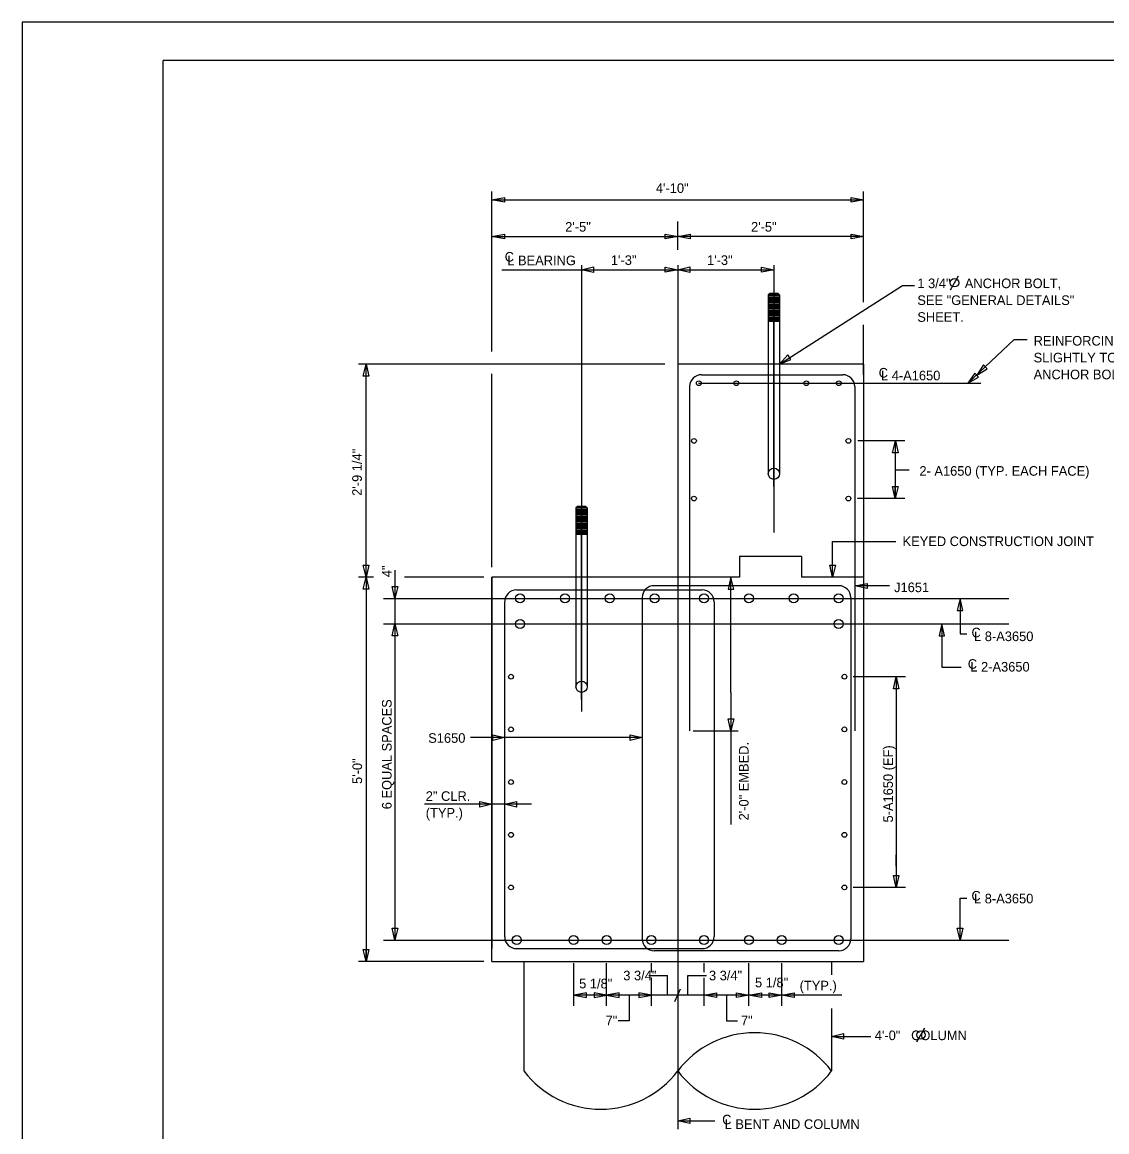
# Model space of a CAD drawing. Extents: x 1970675.2 to 1970711.3, y 796145.2 to 796167.2.
# Drawn here: x 1970675.24 to 1970689.34, y 796152.81 to 796167.25 of the extents above; entities that cross this region are included whole.
import ezdxf

# ---------------------------------------------------------------- set-up
doc = ezdxf.new("R2010")
doc.units = 0
for name, color, linetype in [('BR_AUTO DIMENSION', 7, 'Continuous'), ('BR_BORDER LINES', 7, 'Continuous'), ('BR_CENTER LINES', 7, 'Continuous'), ('BR_CONCRETE', 7, 'Continuous'), ('BR_REBAR', 7, 'Continuous'), ('BR_STRUCTURAL STEEL', 7, 'Continuous'), ('BR_TEXT', 7, 'Continuous'), ('Level 31', 7, 'Continuous')]:
    doc.layers.add(name, color=color, linetype=linetype)

msp = doc.modelspace()

# ---------------------------------------------------------------- linework, layer by layer
at = {"layer": 'BR_AUTO DIMENSION'}
for p, q in [((1970681.342, 796162.965), (1970681.342, 796165.043)), ((1970686.176, 796163.606), (1970686.176, 796165.043)), ((1970681.342, 796164.935), (1970686.176, 796164.935)), ((1970683.759, 796164.287), (1970683.759, 796164.655)), ((1970681.342, 796164.46), (1970683.759, 796164.46)), ((1970686.176, 796164.46), (1970683.759, 796164.46)), ((1970681.473, 796164.027), (1970682.509, 796164.027)), ((1970682.509, 796164.027), (1970683.759, 796164.027)), ((1970683.759, 796164.027), (1970685.009, 796164.027)), ((1970685.082, 796162.8), (1970686.682, 796163.82)), ((1970686.682, 796163.82), (1970686.836, 796163.82)), ((1970686.176, 796162.658), (1970686.176, 796163.31)), ((1970683.592, 796162.8), (1970679.609, 796162.8)), ((1970679.707, 796160.029), (1970679.707, 796162.8)), ((1970681.342, 796160.158), (1970681.342, 796162.671)), ((1970686.712, 796161.8), (1970686.1, 796161.8)), ((1970686.588, 796161.8), (1970686.588, 796161.05)), ((1970686.588, 796161.423), (1970686.766, 796161.423)), ((1970686.712, 796161.05), (1970686.097, 796161.05)), ((1970680.082, 796160.119), (1970680.082, 796155.307)), ((1970679.802, 796160.029), (1970679.609, 796160.029)), ((1970679.707, 796160.029), (1970679.707, 796155.029)), ((1970681.238, 796160.029), (1970680.205, 796160.029)), ((1970684.451, 796158.529), (1970684.451, 796160.029)), ((1970686.513, 796159.913), (1970686.06, 796159.913)), ((1970687.192, 796159.419), (1970687.192, 796158.857)), ((1970687.192, 796158.857), (1970687.443, 796158.857)), ((1970686.722, 796158.733), (1970686.04, 796158.733)), ((1970686.599, 796158.733), (1970686.599, 796155.992)), ((1970684.451, 796158.529), (1970684.451, 796156.811)), ((1970683.961, 796158.029), (1970684.543, 796158.029)), ((1970683.296, 796157.941), (1970681.063, 796157.941)), ((1970681.86, 796157.074), (1970680.468, 796157.074)), ((1970686.722, 796155.992), (1970686.04, 796155.992)), ((1970681.238, 796155.029), (1970679.609, 796155.029)), ((1970682.407, 796154.454), (1970682.407, 796155.006)), ((1970682.834, 796154.454), (1970682.834, 796155.006)), ((1970683.417, 796154.891), (1970683.417, 796155.006)), ((1970684.101, 796154.891), (1970684.101, 796155.006)), ((1970684.684, 796154.454), (1970684.684, 796155.006)), ((1970685.111, 796154.454), (1970685.111, 796155.006)), ((1970683.384, 796154.846), (1970683.627, 796154.846)), ((1970683.417, 796154.454), (1970683.417, 796154.815)), ((1970683.627, 796154.592), (1970683.627, 796154.846)), ((1970683.891, 796154.846), (1970684.134, 796154.846)), ((1970683.891, 796154.592), (1970683.891, 796154.846)), ((1970684.101, 796154.454), (1970684.101, 796154.815)), ((1970683.722, 796154.509), (1970683.796, 796154.674)), ((1970685.894, 796154.592), (1970682.407, 796154.592)), ((1970683.127, 796154.592), (1970683.127, 796154.259)), ((1970684.393, 796154.592), (1970684.393, 796154.259)), ((1970683.127, 796154.259), (1970682.983, 796154.259)), ((1970684.393, 796154.259), (1970684.537, 796154.259)), ((1970685.759, 796154.055), (1970686.271, 796154.055)), ((1970683.759, 796152.956), (1970684.242, 796152.956))]:
    msp.add_line(p, q, dxfattribs=at)
for points in [[(1970681.505, 796164.904), (1970681.342, 796164.935), (1970681.505, 796164.967)], [(1970686.013, 796164.967), (1970686.176, 796164.935), (1970686.013, 796164.904)], [(1970681.505, 796164.429), (1970681.342, 796164.46), (1970681.505, 796164.491)], [(1970683.596, 796164.491), (1970683.759, 796164.46), (1970683.596, 796164.429)], [(1970683.921, 796164.429), (1970683.759, 796164.46), (1970683.921, 796164.491)], [(1970686.013, 796164.491), (1970686.176, 796164.46), (1970686.013, 796164.429)], [(1970682.665, 796163.991), (1970682.509, 796164.027), (1970682.665, 796164.063)], [(1970683.596, 796164.058), (1970683.759, 796164.027), (1970683.596, 796163.996)], [(1970683.915, 796163.991), (1970683.759, 796164.027), (1970683.915, 796164.063)], [(1970684.846, 796164.058), (1970685.009, 796164.027), (1970684.846, 796163.996)], [(1970685.189, 796162.919), (1970685.082, 796162.8), (1970685.23, 796162.86)], [(1970679.671, 796162.644), (1970679.707, 796162.8), (1970679.743, 796162.644)], [(1970687.735, 796162.79), (1970687.646, 796162.657), (1970687.784, 796162.738)], [(1970687.621, 796162.683), (1970687.532, 796162.55), (1970687.67, 796162.631)], [(1970686.553, 796161.644), (1970686.589, 796161.8), (1970686.625, 796161.644)], [(1970686.624, 796161.206), (1970686.588, 796161.05), (1970686.552, 796161.206)], [(1970679.743, 796160.185), (1970679.707, 796160.029), (1970679.671, 796160.185)], [(1970685.809, 796160.185), (1970685.773, 796160.029), (1970685.737, 796160.185)], [(1970679.671, 796159.873), (1970679.707, 796160.029), (1970679.743, 796159.873)], [(1970684.487, 796159.873), (1970684.451, 796160.029), (1970684.415, 796159.873)], [(1970680.118, 796159.908), (1970680.082, 796159.752), (1970680.046, 796159.908)], [(1970686.222, 796159.882), (1970686.06, 796159.913), (1970686.222, 796159.944)], [(1970687.465, 796159.596), (1970687.429, 796159.752), (1970687.393, 796159.596)], [(1970680.046, 796159.263), (1970680.082, 796159.419), (1970680.118, 796159.263)], [(1970687.228, 796159.263), (1970687.192, 796159.419), (1970687.156, 796159.263)], [(1970686.563, 796158.577), (1970686.599, 796158.733), (1970686.635, 796158.577)], [(1970684.487, 796158.185), (1970684.451, 796158.029), (1970684.415, 796158.185)], [(1970681.353, 796157.977), (1970681.509, 796157.941), (1970681.353, 796157.905)], [(1970683.14, 796157.977), (1970683.296, 796157.941), (1970683.14, 796157.905)], [(1970681.186, 796157.11), (1970681.342, 796157.074), (1970681.186, 796157.038)], [(1970681.665, 796157.038), (1970681.509, 796157.074), (1970681.665, 796157.11)], [(1970686.635, 796156.148), (1970686.599, 796155.992), (1970686.563, 796156.148)], [(1970680.118, 796155.463), (1970680.082, 796155.307), (1970680.046, 796155.463)], [(1970687.465, 796155.463), (1970687.429, 796155.307), (1970687.393, 796155.463)], [(1970679.743, 796155.185), (1970679.707, 796155.029), (1970679.671, 796155.185)], [(1970682.575, 796154.623), (1970682.413, 796154.592), (1970682.575, 796154.56)], [(1970682.671, 796154.56), (1970682.834, 796154.592), (1970682.671, 796154.623)], [(1970682.996, 796154.623), (1970682.834, 796154.592), (1970682.996, 796154.56)], [(1970683.254, 796154.56), (1970683.417, 796154.592), (1970683.254, 796154.623)], [(1970684.263, 796154.56), (1970684.101, 796154.592), (1970684.263, 796154.623)], [(1970684.522, 796154.623), (1970684.684, 796154.592), (1970684.522, 796154.56)], [(1970684.847, 796154.56), (1970684.684, 796154.592), (1970684.847, 796154.623)], [(1970684.949, 796154.623), (1970685.111, 796154.592), (1970684.949, 796154.56)], [(1970685.274, 796154.56), (1970685.111, 796154.592), (1970685.274, 796154.623)], [(1970685.915, 796154.019), (1970685.759, 796154.055), (1970685.915, 796154.091)], [(1970683.915, 796152.92), (1970683.759, 796152.956), (1970683.915, 796152.992)]]:
    msp.add_lwpolyline(points, close=True, dxfattribs=at)
for points in [[(1970687.532, 796162.55), (1970688.135, 796163.118), (1970688.3, 796163.118)], [(1970685.773, 796160.029), (1970685.773, 796160.492), (1970686.594, 796160.492)], [(1970687.429, 796159.752), (1970687.429, 796159.289), (1970687.517, 796159.289)], [(1970687.429, 796155.307), (1970687.429, 796155.853), (1970687.517, 796155.853)]]:
    msp.add_lwpolyline(points, dxfattribs=at)
at = {"layer": 'BR_BORDER LINES'}
for p in [(1970710.736, 796166.746), (1970677.07, 796145.746)]:
    msp.add_line(p, (1970677.07, 796166.746), dxfattribs=at)
at = {"layer": 'BR_CENTER LINES'}
for p, q in [((1970682.509, 796164.087), (1970682.509, 796158.28)), ((1970683.759, 796164.087), (1970683.759, 796152.849)), ((1970685.009, 796164.087), (1970685.009, 796160.609)), ((1970685.009, 796161.207), (1970685.009, 796163.506)), ((1970684.029, 796162.55), (1970687.699, 796162.55)), ((1970682.509, 796158.436), (1970682.509, 796160.735)), ((1970679.934, 796159.752), (1970688.062, 796159.752)), ((1970679.934, 796159.419), (1970688.062, 796159.419)), ((1970679.934, 796155.307), (1970688.062, 796155.307))]:
    msp.add_line(p, q, dxfattribs=at)
at = {"layer": 'BR_CONCRETE'}
for p, q in [((1970683.759, 796162.8), (1970683.759, 796160.029)), ((1970686.176, 796162.8), (1970683.759, 796162.8)), ((1970686.176, 796162.8), (1970686.176, 796160.029)), ((1970684.564, 796160.298), (1970684.564, 796160.029)), ((1970685.37, 796160.298), (1970684.564, 796160.298)), ((1970685.37, 796160.298), (1970685.37, 796160.029)), ((1970681.342, 796160.029), (1970681.342, 796155.196)), ((1970681.342, 796155.029), (1970681.342, 796160.029)), ((1970683.759, 796160.029), (1970681.342, 796160.029)), ((1970684.564, 796160.029), (1970683.759, 796160.029)), ((1970686.176, 796160.029), (1970685.37, 796160.029)), ((1970686.176, 796160.029), (1970686.176, 796155.029)), ((1970681.342, 796155.029), (1970686.176, 796155.029)), ((1970681.759, 796155.029), (1970681.759, 796153.605)), ((1970685.759, 796155.029), (1970685.759, 796154.856)), ((1970685.759, 796154.418), (1970685.759, 796153.605))]:
    msp.add_line(p, q, dxfattribs=at)
for centre, start, end in [((1970684.759, 796152.851), 37.0023, 142.9977), ((1970682.759, 796154.359), 217.0023, 322.9977), ((1970684.759, 796154.359), 217.0023, 322.9977)]:
    msp.add_arc(centre, 1.252, start, end, dxfattribs=at)
at = {"layer": 'BR_REBAR'}
for p, q in [((1970684.067, 796162.661), (1970685.906, 796162.661)), ((1970683.914, 796162.508), (1970683.914, 796158.029)), ((1970686.06, 796162.508), (1970686.06, 796158.029)), ((1970681.663, 796159.863), (1970684.076, 796159.863)), ((1970685.855, 796159.917), (1970683.452, 796159.917)), ((1970681.509, 796159.709), (1970681.509, 796155.35)), ((1970683.296, 796159.761), (1970683.296, 796155.325)), ((1970684.233, 796159.707), (1970684.233, 796155.352)), ((1970686.009, 796159.764), (1970686.009, 796155.323)), ((1970681.662, 796155.196), (1970684.076, 796155.196)), ((1970685.855, 796155.169), (1970683.452, 796155.169))]:
    msp.add_line(p, q, dxfattribs=at)
for centre, radius in [((1970684.033, 796162.55), 0.0313), ((1970684.521, 796162.55), 0.0313), ((1970685.431, 796162.55), 0.0313), ((1970685.853, 796162.55), 0.0313), ((1970683.97, 796161.8), 0.0313), ((1970685.978, 796161.8), 0.0313), ((1970683.97, 796161.05), 0.0313), ((1970685.978, 796161.05), 0.0313), ((1970681.71, 796159.752), 0.0588), ((1970682.293, 796159.752), 0.0588), ((1970682.876, 796159.752), 0.0588), ((1970683.46, 796159.752), 0.0588), ((1970684.101, 796159.752), 0.0588), ((1970684.684, 796159.752), 0.0588), ((1970685.267, 796159.752), 0.0588), ((1970685.851, 796159.752), 0.0588), ((1970681.71, 796159.419), 0.0588), ((1970685.851, 796159.419), 0.0588), ((1970681.592, 796158.733), 0.0313), ((1970685.926, 796158.733), 0.0313), ((1970681.592, 796158.048), 0.0313), ((1970685.926, 796158.048), 0.0313), ((1970681.592, 796157.363), 0.0313), ((1970685.926, 796157.363), 0.0313), ((1970681.592, 796156.677), 0.0313), ((1970685.926, 796156.677), 0.0313), ((1970681.592, 796155.992), 0.0313), ((1970685.926, 796155.992), 0.0313), ((1970681.667, 796155.307), 0.0588), ((1970682.404, 796155.307), 0.0588), ((1970682.834, 796155.307), 0.0588), ((1970683.417, 796155.307), 0.0588), ((1970684.101, 796155.307), 0.0588), ((1970684.684, 796155.307), 0.0588), ((1970685.112, 796155.307), 0.0588), ((1970685.851, 796155.307), 0.0588)]:
    msp.add_circle(centre, radius, dxfattribs=at)
for centre, start, end in [((1970684.07, 796162.505), 91.025, 178.975), ((1970685.904, 796162.505), 1.025, 88.975), ((1970681.665, 796159.707), 91.025, 178.975), ((1970683.452, 796159.761), 90, 180), ((1970684.076, 796159.707), 0, 90), ((1970685.853, 796159.761), 1.025, 88.975), ((1970681.665, 796155.352), 181.025, 268.975), ((1970683.452, 796155.325), 180, 270), ((1970684.076, 796155.352), 270, 0), ((1970685.853, 796155.325), 271.025, 358.975)]:
    msp.add_arc(centre, 0.156, start, end, dxfattribs=at)
at = {"layer": 'BR_STRUCTURAL STEEL'}
for p, q in [((1970684.954, 796163.717), (1970684.936, 796163.699)), ((1970685.082, 796163.699), (1970684.936, 796163.699)), ((1970684.936, 796163.699), (1970684.936, 796162.8)), ((1970685.082, 796163.681), (1970684.936, 796163.681)), ((1970685.082, 796163.662), (1970684.936, 796163.662)), ((1970685.082, 796163.644), (1970684.936, 796163.644)), ((1970685.082, 796163.626), (1970684.936, 796163.626)), ((1970685.082, 796163.608), (1970684.936, 796163.608)), ((1970685.082, 796163.59), (1970684.936, 796163.59)), ((1970685.064, 796163.717), (1970684.954, 796163.717)), ((1970685.082, 796163.699), (1970685.064, 796163.717)), ((1970685.082, 796163.699), (1970685.082, 796162.8)), ((1970685.082, 796163.571), (1970684.936, 796163.571)), ((1970685.082, 796163.553), (1970684.936, 796163.553)), ((1970685.082, 796163.535), (1970684.936, 796163.535)), ((1970685.082, 796163.517), (1970684.936, 796163.517)), ((1970685.082, 796163.498), (1970684.936, 796163.498)), ((1970685.082, 796163.48), (1970684.936, 796163.48)), ((1970685.082, 796163.462), (1970684.936, 796163.462)), ((1970685.082, 796163.444), (1970684.936, 796163.444)), ((1970685.082, 796163.426), (1970684.936, 796163.426)), ((1970685.082, 796163.407), (1970684.936, 796163.407)), ((1970685.082, 796163.389), (1970684.936, 796163.389)), ((1970685.082, 796163.371), (1970684.936, 796163.371)), ((1970685.082, 796163.353), (1970684.936, 796163.353)), ((1970684.936, 796162.8), (1970684.936, 796161.373)), ((1970685.082, 796162.8), (1970685.082, 796161.376)), ((1970682.454, 796160.946), (1970682.436, 796160.928)), ((1970682.582, 796160.928), (1970682.436, 796160.928)), ((1970682.436, 796160.928), (1970682.436, 796160.029)), ((1970682.582, 796160.91), (1970682.436, 796160.91)), ((1970682.582, 796160.892), (1970682.436, 796160.892)), ((1970682.582, 796160.873), (1970682.436, 796160.873)), ((1970682.582, 796160.855), (1970682.436, 796160.855)), ((1970682.582, 796160.837), (1970682.436, 796160.837)), ((1970682.564, 796160.946), (1970682.454, 796160.946)), ((1970682.582, 796160.928), (1970682.564, 796160.946)), ((1970682.582, 796160.928), (1970682.582, 796160.029)), ((1970682.582, 796160.819), (1970682.436, 796160.819)), ((1970682.582, 796160.801), (1970682.436, 796160.801)), ((1970682.582, 796160.782), (1970682.436, 796160.782)), ((1970682.582, 796160.764), (1970682.436, 796160.764)), ((1970682.582, 796160.746), (1970682.436, 796160.746)), ((1970682.582, 796160.728), (1970682.436, 796160.728)), ((1970682.582, 796160.709), (1970682.436, 796160.709)), ((1970682.582, 796160.691), (1970682.436, 796160.691)), ((1970682.582, 796160.673), (1970682.436, 796160.673)), ((1970682.582, 796160.655), (1970682.436, 796160.655)), ((1970682.582, 796160.636), (1970682.436, 796160.636)), ((1970682.582, 796160.618), (1970682.436, 796160.618)), ((1970682.582, 796160.6), (1970682.436, 796160.6)), ((1970682.582, 796160.582), (1970682.436, 796160.582)), ((1970682.436, 796160.029), (1970682.436, 796158.602)), ((1970682.582, 796160.029), (1970682.582, 796158.605))]:
    msp.add_line(p, q, dxfattribs=at)
for centre in [(1970685.009, 796161.373), (1970682.509, 796158.602)]:
    msp.add_circle(centre, 0.0729, dxfattribs=at)
at = {"layer": 'BR_TEXT'}
for p, q in [((1970687.304, 796163.767), (1970687.409, 796163.948)), ((1970686.588, 796161.05), (1970686.588, 796161.198)), ((1970686.599, 796156.27), (1970686.599, 796156.418)), ((1970679.707, 796155.029), (1970679.707, 796155.177)), ((1970686.868, 796153.982), (1970686.973, 796154.164))]:
    msp.add_line(p, q, dxfattribs=at)
for centre in [(1970687.357, 796163.858), (1970686.921, 796154.073)]:
    msp.add_circle(centre, 0.055, dxfattribs=at)
at = {"layer": 'Level 31'}
msp.add_lwpolyline([(1970675.236, 796145.246), (1970711.236, 796145.246), (1970711.236, 796167.246), (1970675.236, 796167.246)], close=True, dxfattribs=at)

# ---------------------------------------------------------------- texts
at = {"layer": 'BR_AUTO DIMENSION'}
for s, p in [('4\'-10"', (1970683.475, 796165.025)), ('2\'-5"', (1970682.296, 796164.522)), ('2\'-5"', (1970684.712, 796164.522))]:
    msp.add_text(s, height=0.125, dxfattribs=at).set_placement(p)
at = {"layer": 'BR_TEXT'}
for s, p in [('C', (1970681.51, 796164.132)), ('L BEARING', (1970681.543, 796164.085)), ('1\'-3"', (1970682.89, 796164.089)), ('1\'-3"', (1970684.14, 796164.089)), ('C', (1970686.372, 796162.624)), ('L 4-A1650', (1970686.402, 796162.588)), ('2- A1650 (TYP. EACH FACE)', (1970686.901, 796161.347)), ('KEYED CONSTRUCTION JOINT', (1970686.682, 796160.432)), ('J1651', (1970686.572, 796159.833)), ('S1650', (1970680.515, 796157.873)), ('2" CLR.', (1970680.483, 796157.118)), ('(TYP.)', (1970680.483, 796156.9)), ('3 3/4"', (1970683.051, 796154.784)), ('3 3/4"', (1970684.165, 796154.784))]:
    msp.add_text(s, height=0.125, dxfattribs=at).set_placement(p)
for s, rotation, p in [('1 3/4"    ANCHOR BOLT, ', 360, (1970686.874, 796163.787)), ('SEE "GENERAL DETAILS"', 360, (1970686.874, 796163.568)), ('SHEET.', 360, (1970686.874, 796163.349)), ('REINFORCING MAY BE ADJUSTED', 360, (1970688.386, 796163.04)), ('SLIGHTLY TO CLEAR 1 3/4"  ', 360, (1970688.386, 796162.821)), ('ANCHOR BOLTS', 360, (1970688.386, 796162.602)), ('2\'-9 1/4"', 90, (1970679.652, 796161.086)), ('4"', 90, (1970680.039, 796160.027)), ('C', 360, (1970687.578, 796159.245)), ('L 8-A3650', 360, (1970687.612, 796159.196)), ('C', 360, (1970687.53, 796158.836)), ('L 2-A3650', 360, (1970687.563, 796158.8)), ('6 EQUAL SPACES', 90, (1970680.039, 796157.009)), ('2\'-0" EMBED.', 90, (1970684.68, 796156.864)), ('5-A1650 (EF)', 90, (1970686.557, 796156.837)), ('5\'-0"', 90, (1970679.655, 796157.338)), ('C', 360, (1970687.578, 796155.821)), ('L 8-A3650', 360, (1970687.611, 796155.785)), ('5 1/8"', 360, (1970682.477, 796154.679)), ('5 1/8"', 360, (1970684.764, 796154.693)), ('(TYP.)', 360, (1970685.344, 796154.653)), ('7"', 360, (1970682.821, 796154.198)), ('7"', 360, (1970684.581, 796154.198)), ('4\'-0"   COLUMN', 360, (1970686.321, 796154.006)), ('C', 360, (1970684.337, 796152.91)), ('L BENT AND COLUMN', 360, (1970684.369, 796152.851))]:
    msp.add_text(s, height=0.125, rotation=rotation, dxfattribs=at).set_placement(p)

doc.saveas('drawing.dxf')
